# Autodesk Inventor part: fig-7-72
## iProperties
Created: 2004-05
Part Number: fig-7-72
Document SubType Name: Modeling
Designer: CADCIM Technologies
Manufacturer: Standard
Standards Organization: Custom
Author: CADCIM Technologies
